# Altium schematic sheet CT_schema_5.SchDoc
size 479 x 328 mm
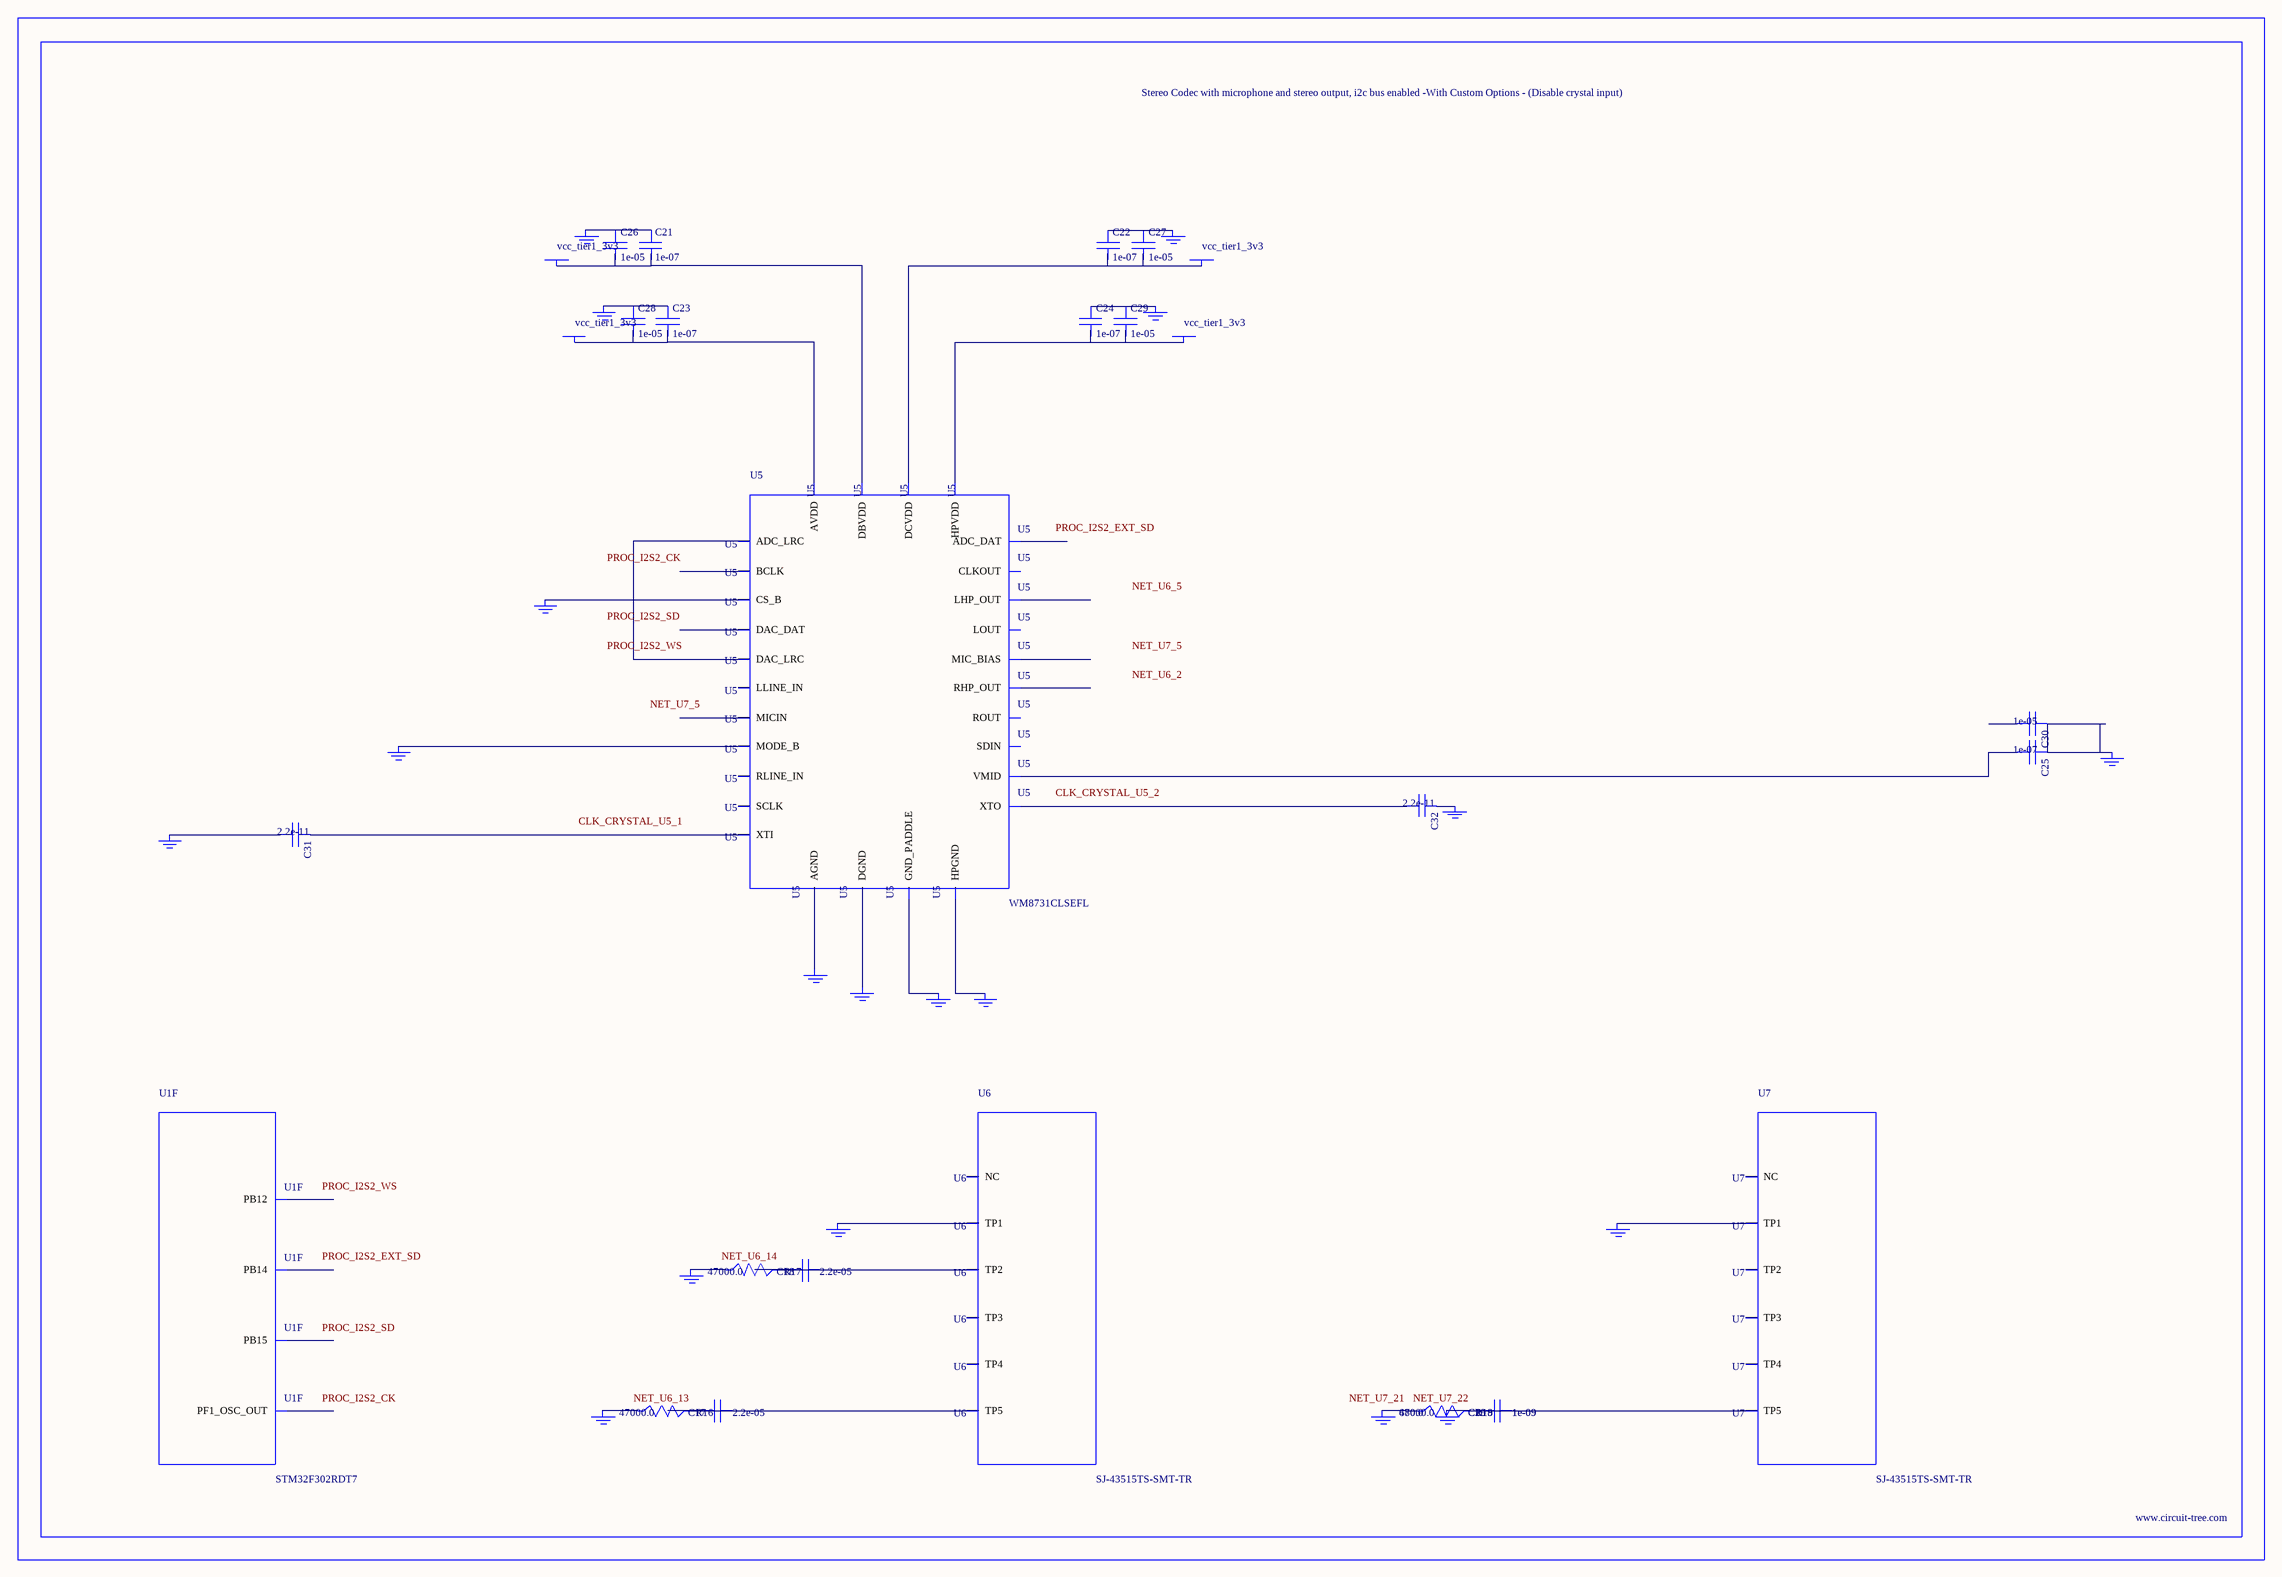
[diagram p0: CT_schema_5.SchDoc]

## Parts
BORDER4  (no value)
C17  2.2e-05  [C1210]
C18  2.2e-05  [C1210]
C19  1e-09  [C0402]
C20  1e-09  [C0402]
C21  1e-07  [C0402]
C22  1e-07  [C0402]
C23  1e-07  [C0402]
C24  1e-07  [C0402]
C25  1e-07  [C0402]
C26  1e-05  [C0805]
C27  1e-05  [C0805]
C28  1e-05  [C0805]
C29  1e-05  [C0805]
C30  1e-05  [C0805]
C31  2.2e-11  [C0402]
C32  2.2e-11  [C0402]
GND_INSTANCE_4_0  (no value)
GND_INSTANCE_4_1  (no value)
GND_INSTANCE_4_2  (no value)
GND_INSTANCE_4_3  (no value)
GND_INSTANCE_4_4  (no value)
GND_INSTANCE_4_5  (no value)
GND_INSTANCE_4_6  (no value)
GND_INSTANCE_4_7  (no value)
GND_INSTANCE_4_8  (no value)
GND_INSTANCE_4_9  (no value)
GND_INSTANCE_4_10  (no value)
GND_INSTANCE_4_11  (no value)
GND_INSTANCE_4_12  (no value)
GND_INSTANCE_4_13  (no value)
GND_INSTANCE_4_14  (no value)
GND_INSTANCE_4_15  (no value)
GND_INSTANCE_4_16  (no value)
GND_INSTANCE_4_17  (no value)
GND_INSTANCE_4_18  (no value)
POWER_INSTANCE_4_0  vcc_tier1_3v3
POWER_INSTANCE_4_1  vcc_tier1_3v3
POWER_INSTANCE_4_2  vcc_tier1_3v3
POWER_INSTANCE_4_3  vcc_tier1_3v3
R16  47000.0  [R0603]
R17  47000.0  [R0603]
R18  47000.0  [R0603]
R19  680.0  [R0603]
U1  STM32F302RDT7  [LQFP64]  (part F of 7)
U5  WM8731CLSEFL  [QFN-28]
U6  SJ-43515TS-SMT-TR  [SJ-43515TS-SMT-TR]
U7  SJ-43515TS-SMT-TR  [SJ-43515TS-SMT-TR]

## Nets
NetC17_1: C17.1 C17.2 R16.2 U6.5(TP5)
NetC18_1: C18.1 C18.2 R17.2 U6.2(TP2)
NetC19_1: C19.1 C19.2 C20.1 C20.2 GND_INSTANCE_4_18.0(GND) R18.2 R19.2 U7.5(TP5)
NetC21_1: C21.1 C26.1 GND_INSTANCE_4_3.0(GND)
NetC21_2: C21.2 C26.2 POWER_INSTANCE_4_1.0(PWR) U5.5(DBVDD)
NetC22_1: C22.1 C27.1 GND_INSTANCE_4_2.0(GND)
NetC22_2: C22.2 C27.2 POWER_INSTANCE_4_0.0(PWR) U5.3(DCVDD)
NetC23_1: C23.1 C28.1 GND_INSTANCE_4_6.0(GND)
NetC23_2: C23.2 C28.2 POWER_INSTANCE_4_3.0(PWR) U5.18(AVDD)
NetC24_1: C24.1 C29.1 GND_INSTANCE_4_4.0(GND)
NetC24_2: C24.2 C29.2 POWER_INSTANCE_4_2.0(PWR) U5.12(HPVDD)
NetC25_1: C25.1 C30.1 GND_INSTANCE_4_7.0(GND)
NetC25_2: C25.2 U5.20(VMID)
NetC31_1: C31.1 U5.1(XTI)
NetC31_2: C31.2 GND_INSTANCE_4_0.0(GND)
NetC32_1: C32.1 GND_INSTANCE_4_1.0(GND)
NetC32_2: C32.2 U5.2(XTO)
NetGND_INSTANCE_4_5_0: GND_INSTANCE_4_5.0(GND) U5.15(HPGND)
NetGND_INSTANCE_4_8_0: GND_INSTANCE_4_8.0(GND) U5.25(MODE_B)
NetGND_INSTANCE_4_9_0: GND_INSTANCE_4_9.0(GND) U5.26(CS_B)
NetGND_INSTANCE_4_10_0: GND_INSTANCE_4_10.0(GND) U5.29(GND_PADDLE)
NetGND_INSTANCE_4_11_0: GND_INSTANCE_4_11.0(GND) U5.4(DGND)
NetGND_INSTANCE_4_12_0: GND_INSTANCE_4_12.0(GND) U5.19(AGND)
NetGND_INSTANCE_4_13_0: GND_INSTANCE_4_13.0(GND) U6.1(TP1)
NetGND_INSTANCE_4_14_0: GND_INSTANCE_4_14.0(GND) R17.1
NetGND_INSTANCE_4_15_0: GND_INSTANCE_4_15.0(GND) R16.1
NetGND_INSTANCE_4_16_0: GND_INSTANCE_4_16.0(GND) U7.1(TP1)
NetGND_INSTANCE_4_17_0: GND_INSTANCE_4_17.0(GND) R18.1 R19.1
NetU5_9: U5.9(DAC_LRC) U5.11(ADC_LRC)

Not connected (* = marked no-connect by the designer): C30 2; U1 6(PF1_OSC_OUT) 33(PB12) 35(PB14) 36(PB15); U5 6(CLKOUT) 7(BCLK) 8(DAC_DAT) 10(ADC_DAT) 13(LHP_OUT) 14(RHP_OUT) 16(LOUT) 17(ROUT) 21(MIC_BIAS) 22(MICIN) 23(RLINE_IN) 24(LLINE_IN) 27(SDIN) 28(SCLK); U6 3(TP3) 4(TP4) 6(NC); U7 2(TP2) 3(TP3) 4(TP4) 6(NC)

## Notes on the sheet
- Labels drawn without touching a wire or pin: CLK_CRYSTAL_U5_1, CLK_CRYSTAL_U5_2, NET_U6_2, NET_U6_5, NET_U6_13, NET_U6_14, NET_U7_5, NET_U7_21, NET_U7_22, PROC_I2S2_CK, PROC_I2S2_EXT_SD, PROC_I2S2_SD, PROC_I2S2_WS

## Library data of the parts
BORDER4 = BORDER_PAGE4
C17 C18 = C1210C224K5RACTU
C19 C20 = C0402C102K3RAC
C21-C25 = C0402C104K3RACTU
C26-C30 = C0805C106K8RACTU
C31 C32 = C0402C220K3RAC
GND_INSTANCE_4_0-GND_INSTANCE_4_18 = GND
POWER_INSTANCE_4_0-POWER_INSTANCE_4_3 = PWR
R16-R18 = RC0603JR-0747KL
R19 = RC0603JR-07680RL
